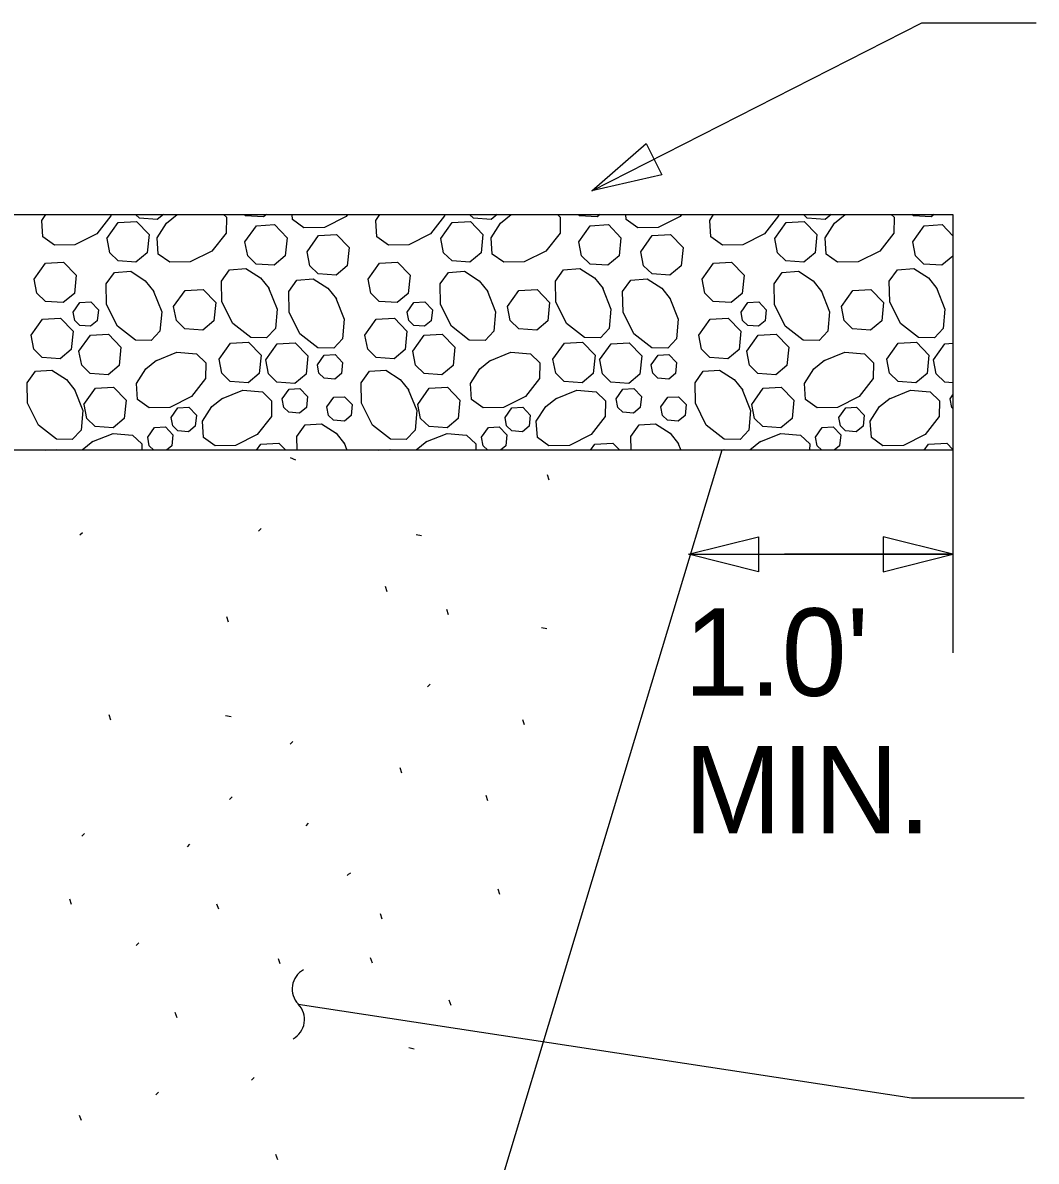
# Model space of a CAD drawing. Extents: x 9786.6 to 9853.1, y 9958.7 to 10011.2.
# Drawn here: x 9816.93 to 9829.04, y 9997.08 to 10010.67 of the extents above; entities that cross this region are included whole.
import ezdxf

# ---------------------------------------------------------------- set-up
doc = ezdxf.new("R2010")
doc.units = 0
for name, color, linetype in [('Default', 7, 'Continuous'), ('G-ANNO-TEXT', 7, 'Continuous'), ('G-ANNO-TTXT', 7, 'Continuous'), ('G-DETL-LINE', 7, 'Continuous'), ('G-DETL-OTLN', 7, 'Continuous'), ('G-DETL-PATT', 7, 'Continuous')]:
    doc.layers.add(name, color=color, linetype=linetype)

# ---------------------------------------------------------------- blocks, each defined once
blk = doc.blocks.new('TERARR')
at = {"layer": 'Default'}
blk.add_lwpolyline([(-0.667, 0.167), (0, 0), (-0.667, -0.167)], close=True, dxfattribs=at)
blk = doc.blocks.new('TERBRK')
at = {"layer": 'Default'}
for centre, start, end in [((0.125, 0.167), 126.8699, 233.1301), ((-0.125, -0.167), 306.8699, 53.1301)]:
    blk.add_arc(centre, 0.208, start, end, dxfattribs=at)

msp = doc.modelspace()

# ---------------------------------------------------------------- linework, layer by layer
at = {"layer": 'Default'}
for points in [[(9818.77, 10008.375), (9818.792, 10008.384)], [(9822.758, 10008.375), (9822.78, 10008.384)], [(9823.833, 10008.384), (9823.797, 10008.354), (9823.583, 10008.369), (9823.568, 10008.384)], [(9826.746, 10008.375), (9826.768, 10008.384)], [(9817.201, 10005.569), (9817.332, 10005.576), (9817.339, 10005.569)], [(9821.189, 10005.569), (9821.32, 10005.576), (9821.327, 10005.569)], [(9825.177, 10005.569), (9825.308, 10005.576), (9825.315, 10005.569)]]:
    msp.add_lwpolyline(points, dxfattribs=at)
at = {"layer": 'G-ANNO-TEXT'}
for p, q in [((9828.045, 10005.569), (9828.045, 10003.15)), ((9824.888, 10004.326), (9828.045, 10004.326)), ((9828.045, 10004.326), (9826.035, 10004.326))]:
    msp.add_line(p, q, dxfattribs=at)
msp.add_lwpolyline([(9823.731, 10008.667), (9827.674, 10010.673), (9829.04, 10010.673)], dxfattribs=at)
at = {"layer": 'G-ANNO-TTXT'}
msp.add_lwpolyline([(9820.226, 9998.953), (9827.551, 9997.834), (9828.894, 9997.834)], dxfattribs=at)
at = {"layer": 'G-DETL-LINE'}
msp.add_lwpolyline([(9804.677, 10008.384), (9828.045, 10008.384), (9828.045, 10005.569), (9804.677, 10005.569)], close=True, dxfattribs=at)
at = {"layer": 'G-DETL-OTLN'}
msp.add_lwpolyline([(9825.286, 10005.569), (9820.093, 9988.373), (9820.093, 9984.842), (9813.116, 9984.842), (9813.116, 9988.373), (9807.923, 10005.569)], dxfattribs=at)
at = {"layer": 'G-DETL-PATT'}
for p, q in [((9820.129, 10005.483), (9820.192, 10005.452)), ((9823.222, 10005.212), (9823.201, 10005.275)), ((9817.617, 10004.557), (9817.648, 10004.588)), ((9819.751, 10004.603), (9819.782, 10004.635)), ((9821.634, 10004.564), (9821.699, 10004.55)), ((9821.287, 10003.877), (9821.266, 10003.94)), ((9822.021, 10003.604), (9822, 10003.667)), ((9819.393, 10003.516), (9819.372, 10003.579)), ((9823.129, 10003.453), (9823.193, 10003.439)), ((9821.768, 10002.744), (9821.8, 10002.775)), ((9817.987, 10002.347), (9817.966, 10002.41)), ((9819.358, 10002.401), (9819.423, 10002.387)), ((9822.929, 10002.288), (9822.908, 10002.351)), ((9820.129, 10002.058), (9820.16, 10002.09)), ((9821.463, 10001.713), (9821.442, 10001.776)), ((9819.405, 10001.399), (9819.436, 10001.43)), ((9822.49, 10001.382), (9822.469, 10001.445)), ((9820.318, 10001.084), (9820.349, 10001.116)), ((9817.641, 10000.959), (9817.672, 10000.99)), ((9818.901, 10000.833), (9818.932, 10000.864)), ((9820.821, 10000.504), (9820.809, 10000.49)), ((9820.848, 10000.518), (9820.821, 10000.504)), ((9817.517, 10000.146), (9817.496, 10000.209)), ((9822.635, 10000.263), (9822.614, 10000.326)), ((9819.275, 10000.087), (9819.254, 10000.15)), ((9821.228, 9999.97), (9821.207, 10000.033)), ((9818.291, 9999.656), (9818.322, 9999.687)), ((9820.009, 9999.435), (9819.988, 9999.497)), ((9821.111, 9999.444), (9821.09, 9999.507)), ((9822.05, 9998.937), (9822.029, 9999)), ((9818.778, 9998.791), (9818.757, 9998.854)), ((9821.546, 9998.436), (9821.611, 9998.422)), ((9819.668, 9998.048), (9819.7, 9998.079)), ((9818.525, 9997.872), (9818.557, 9997.904)), ((9817.635, 9997.563), (9817.614, 9997.626)), ((9819.98, 9997.095), (9819.958, 9997.158))]:
    msp.add_line(p, q, dxfattribs=at)
for points in [[(9817.986, 10008.384), (9817.986, 10008.366), (9817.818, 10008.152), (9817.558, 10008.022), (9817.314, 10008.018), (9817.176, 10008.115), (9817.163, 10008.31), (9817.21, 10008.384)], [(9818.614, 10008.384), (9818.542, 10008.324), (9818.329, 10008.34), (9818.283, 10008.384)], [(9819.332, 10008.384), (9819.367, 10008.35), (9819.363, 10008.161), (9819.195, 10007.947), (9818.936, 10007.817), (9818.691, 10007.813), (9818.553, 10007.91), (9818.54, 10008.105), (9818.652, 10008.28), (9818.78, 10008.382)], [(9819.845, 10008.384), (9819.809, 10008.354), (9819.595, 10008.369), (9819.58, 10008.384)], [(9820.815, 10008.384), (9820.796, 10008.36), (9820.537, 10008.23), (9820.292, 10008.226), (9820.155, 10008.324), (9820.151, 10008.384)], [(9821.975, 10008.384), (9821.974, 10008.366), (9821.806, 10008.152), (9821.547, 10008.022), (9821.302, 10008.018), (9821.164, 10008.115), (9821.151, 10008.31), (9821.199, 10008.384)], [(9822.602, 10008.384), (9822.531, 10008.324), (9822.317, 10008.34), (9822.272, 10008.384)], [(9823.32, 10008.384), (9823.355, 10008.35), (9823.352, 10008.161), (9823.184, 10007.947), (9822.924, 10007.817), (9822.679, 10007.813), (9822.542, 10007.91), (9822.529, 10008.105), (9822.64, 10008.28), (9822.768, 10008.382)], [(9824.804, 10008.384), (9824.785, 10008.36), (9824.525, 10008.23), (9824.281, 10008.226), (9824.143, 10008.324), (9824.139, 10008.384)], [(9825.963, 10008.384), (9825.963, 10008.366), (9825.795, 10008.152), (9825.535, 10008.022), (9825.291, 10008.018), (9825.153, 10008.115), (9825.14, 10008.31), (9825.187, 10008.384)], [(9826.59, 10008.384), (9826.519, 10008.324), (9826.305, 10008.34), (9826.26, 10008.384)], [(9827.308, 10008.384), (9827.343, 10008.35), (9827.34, 10008.161), (9827.172, 10007.947), (9826.912, 10007.817), (9826.668, 10007.813), (9826.53, 10007.91), (9826.517, 10008.105), (9826.629, 10008.28), (9826.757, 10008.382)], [(9827.822, 10008.384), (9827.785, 10008.354), (9827.572, 10008.369), (9827.556, 10008.384)], [(9817.94, 10008.095), (9818.076, 10008.288), (9818.292, 10008.3), (9818.443, 10008.144), (9818.421, 10007.926), (9818.287, 10007.814), (9818.074, 10007.83), (9817.973, 10007.927), (9817.941, 10008.095)], [(9819.589, 10008.057), (9819.725, 10008.25), (9819.941, 10008.262), (9820.091, 10008.106), (9820.07, 10007.888), (9819.936, 10007.777), (9819.722, 10007.792), (9819.622, 10007.889), (9819.589, 10008.057)], [(9821.929, 10008.095), (9822.064, 10008.288), (9822.281, 10008.3), (9822.431, 10008.144), (9822.409, 10007.926), (9822.276, 10007.814), (9822.062, 10007.83), (9821.961, 10007.927), (9821.929, 10008.095)], [(9823.577, 10008.057), (9823.713, 10008.25), (9823.929, 10008.262), (9824.08, 10008.106), (9824.058, 10007.888), (9823.924, 10007.777), (9823.711, 10007.792), (9823.61, 10007.889), (9823.578, 10008.057)], [(9825.917, 10008.095), (9826.053, 10008.288), (9826.269, 10008.3), (9826.419, 10008.144), (9826.398, 10007.926), (9826.264, 10007.814), (9826.05, 10007.83), (9825.95, 10007.927), (9825.917, 10008.095)], [(9827.566, 10008.057), (9827.701, 10008.25), (9827.918, 10008.262), (9828.045, 10008.13)], [(9820.33, 10007.939), (9820.466, 10008.132), (9820.682, 10008.144), (9820.832, 10007.988), (9820.81, 10007.77), (9820.677, 10007.659), (9820.463, 10007.674), (9820.363, 10007.771), (9820.33, 10007.939)], [(9824.318, 10007.939), (9824.454, 10008.132), (9824.67, 10008.144), (9824.821, 10007.988), (9824.799, 10007.77), (9824.665, 10007.659), (9824.452, 10007.674), (9824.351, 10007.771), (9824.318, 10007.939)], [(9828.045, 10007.886), (9827.913, 10007.777), (9827.699, 10007.792), (9827.599, 10007.889), (9827.566, 10008.057)], [(9817.071, 10007.611), (9817.207, 10007.804), (9817.423, 10007.816), (9817.574, 10007.66), (9817.552, 10007.442), (9817.418, 10007.331), (9817.205, 10007.346), (9817.104, 10007.444), (9817.072, 10007.611)], [(9821.06, 10007.611), (9821.195, 10007.804), (9821.412, 10007.816), (9821.562, 10007.66), (9821.54, 10007.442), (9821.407, 10007.331), (9821.193, 10007.346), (9821.093, 10007.444), (9821.06, 10007.611)], [(9825.048, 10007.611), (9825.184, 10007.804), (9825.4, 10007.816), (9825.55, 10007.66), (9825.529, 10007.442), (9825.395, 10007.331), (9825.181, 10007.346), (9825.081, 10007.444), (9825.048, 10007.611)], [(9818.494, 10007.475), (9818.594, 10007.222), (9818.574, 10006.989), (9818.469, 10006.878), (9818.28, 10006.882), (9818.065, 10007.05), (9817.936, 10007.309), (9817.931, 10007.554), (9818.029, 10007.692), (9818.224, 10007.705), (9818.398, 10007.593), (9818.5, 10007.465)], [(9819.871, 10007.508), (9819.972, 10007.254), (9819.952, 10007.022), (9819.846, 10006.911), (9819.657, 10006.914), (9819.443, 10007.082), (9819.313, 10007.342), (9819.309, 10007.587), (9819.406, 10007.724), (9819.601, 10007.737), (9819.776, 10007.626), (9819.878, 10007.498)], [(9822.482, 10007.475), (9822.583, 10007.222), (9822.563, 10006.989), (9822.457, 10006.878), (9822.268, 10006.882), (9822.054, 10007.05), (9821.924, 10007.309), (9821.92, 10007.554), (9822.018, 10007.692), (9822.212, 10007.705), (9822.387, 10007.593), (9822.489, 10007.465)], [(9823.859, 10007.508), (9823.96, 10007.254), (9823.94, 10007.022), (9823.835, 10006.911), (9823.646, 10006.914), (9823.431, 10007.082), (9823.301, 10007.342), (9823.297, 10007.587), (9823.395, 10007.724), (9823.59, 10007.737), (9823.764, 10007.626), (9823.866, 10007.498)], [(9826.471, 10007.475), (9826.571, 10007.222), (9826.551, 10006.989), (9826.446, 10006.878), (9826.257, 10006.882), (9826.042, 10007.05), (9825.912, 10007.309), (9825.908, 10007.554), (9826.006, 10007.692), (9826.201, 10007.705), (9826.375, 10007.593), (9826.477, 10007.465)], [(9827.848, 10007.508), (9827.948, 10007.254), (9827.928, 10007.022), (9827.823, 10006.911), (9827.634, 10006.914), (9827.419, 10007.082), (9827.29, 10007.342), (9827.285, 10007.587), (9827.383, 10007.724), (9827.578, 10007.737), (9827.752, 10007.626), (9827.854, 10007.498)], [(9820.674, 10007.385), (9820.775, 10007.132), (9820.755, 10006.899), (9820.65, 10006.788), (9820.461, 10006.791), (9820.246, 10006.959), (9820.116, 10007.219), (9820.112, 10007.464), (9820.21, 10007.601), (9820.405, 10007.614), (9820.579, 10007.503), (9820.681, 10007.375)], [(9824.663, 10007.385), (9824.763, 10007.132), (9824.743, 10006.899), (9824.638, 10006.788), (9824.449, 10006.791), (9824.234, 10006.959), (9824.105, 10007.219), (9824.1, 10007.464), (9824.198, 10007.601), (9824.393, 10007.614), (9824.567, 10007.503), (9824.669, 10007.375)], [(9818.737, 10007.283), (9818.873, 10007.476), (9819.089, 10007.488), (9819.24, 10007.333), (9819.218, 10007.114), (9819.084, 10007.003), (9818.871, 10007.018), (9818.77, 10007.116), (9818.737, 10007.283)], [(9822.726, 10007.283), (9822.861, 10007.476), (9823.078, 10007.488), (9823.228, 10007.333), (9823.206, 10007.114), (9823.073, 10007.003), (9822.859, 10007.018), (9822.758, 10007.116), (9822.726, 10007.283)], [(9826.714, 10007.283), (9826.85, 10007.476), (9827.066, 10007.488), (9827.216, 10007.333), (9827.195, 10007.114), (9827.061, 10007.003), (9826.847, 10007.018), (9826.747, 10007.116), (9826.714, 10007.283)], [(9817.537, 10007.216), (9817.618, 10007.332), (9817.748, 10007.339), (9817.838, 10007.246), (9817.825, 10007.115), (9817.745, 10007.048), (9817.617, 10007.057), (9817.557, 10007.116), (9817.537, 10007.216)], [(9821.525, 10007.216), (9821.607, 10007.332), (9821.737, 10007.339), (9821.827, 10007.246), (9821.814, 10007.115), (9821.734, 10007.048), (9821.605, 10007.057), (9821.545, 10007.116), (9821.525, 10007.216)], [(9825.514, 10007.216), (9825.595, 10007.332), (9825.725, 10007.339), (9825.815, 10007.246), (9825.802, 10007.115), (9825.722, 10007.048), (9825.594, 10007.057), (9825.533, 10007.116), (9825.514, 10007.216)], [(9817.034, 10006.942), (9817.169, 10007.135), (9817.385, 10007.147), (9817.536, 10006.991), (9817.514, 10006.773), (9817.38, 10006.661), (9817.167, 10006.677), (9817.066, 10006.774), (9817.034, 10006.942)], [(9821.022, 10006.942), (9821.157, 10007.135), (9821.374, 10007.147), (9821.524, 10006.991), (9821.502, 10006.773), (9821.369, 10006.661), (9821.155, 10006.677), (9821.055, 10006.774), (9821.022, 10006.942)], [(9825.01, 10006.942), (9825.146, 10007.135), (9825.362, 10007.147), (9825.512, 10006.991), (9825.491, 10006.773), (9825.357, 10006.661), (9825.143, 10006.677), (9825.043, 10006.774), (9825.01, 10006.942)], [(9817.606, 10006.75), (9817.742, 10006.943), (9817.958, 10006.956), (9818.108, 10006.8), (9818.087, 10006.581), (9817.953, 10006.47), (9817.739, 10006.485), (9817.639, 10006.583), (9817.606, 10006.75)], [(9821.594, 10006.75), (9821.73, 10006.943), (9821.946, 10006.956), (9822.097, 10006.8), (9822.075, 10006.581), (9821.941, 10006.47), (9821.728, 10006.485), (9821.627, 10006.583), (9821.595, 10006.75)], [(9825.583, 10006.75), (9825.718, 10006.943), (9825.935, 10006.956), (9826.085, 10006.8), (9826.063, 10006.581), (9825.93, 10006.47), (9825.716, 10006.485), (9825.615, 10006.583), (9825.583, 10006.75)], [(9818.524, 10006.637), (9818.777, 10006.738), (9819.01, 10006.718), (9819.121, 10006.612), (9819.117, 10006.424), (9818.949, 10006.209), (9818.69, 10006.079), (9818.445, 10006.075), (9818.307, 10006.173), (9818.294, 10006.367), (9818.406, 10006.542), (9818.534, 10006.644)], [(9819.28, 10006.655), (9819.415, 10006.848), (9819.632, 10006.86), (9819.782, 10006.704), (9819.76, 10006.486), (9819.627, 10006.374), (9819.413, 10006.39), (9819.312, 10006.487), (9819.28, 10006.655)], [(9819.837, 10006.647), (9819.973, 10006.84), (9820.189, 10006.852), (9820.339, 10006.696), (9820.318, 10006.477), (9820.184, 10006.366), (9819.97, 10006.382), (9819.87, 10006.479), (9819.837, 10006.647)], [(9822.512, 10006.637), (9822.766, 10006.738), (9822.998, 10006.718), (9823.109, 10006.612), (9823.106, 10006.424), (9822.938, 10006.209), (9822.678, 10006.079), (9822.433, 10006.075), (9822.296, 10006.173), (9822.283, 10006.367), (9822.394, 10006.542), (9822.522, 10006.644)], [(9823.268, 10006.655), (9823.404, 10006.848), (9823.62, 10006.86), (9823.77, 10006.704), (9823.748, 10006.486), (9823.615, 10006.374), (9823.401, 10006.39), (9823.301, 10006.487), (9823.268, 10006.655)], [(9823.825, 10006.647), (9823.961, 10006.84), (9824.177, 10006.852), (9824.328, 10006.696), (9824.306, 10006.477), (9824.172, 10006.366), (9823.959, 10006.382), (9823.858, 10006.479), (9823.826, 10006.647)], [(9826.5, 10006.637), (9826.754, 10006.738), (9826.987, 10006.718), (9827.098, 10006.612), (9827.094, 10006.424), (9826.926, 10006.209), (9826.666, 10006.079), (9826.422, 10006.075), (9826.284, 10006.173), (9826.271, 10006.367), (9826.383, 10006.542), (9826.511, 10006.644)], [(9827.256, 10006.655), (9827.392, 10006.848), (9827.608, 10006.86), (9827.759, 10006.704), (9827.737, 10006.486), (9827.603, 10006.374), (9827.39, 10006.39), (9827.289, 10006.487), (9827.256, 10006.655)], [(9827.814, 10006.647), (9827.949, 10006.84), (9828.045, 10006.845)], [(9820.454, 10006.587), (9820.535, 10006.703), (9820.665, 10006.71), (9820.755, 10006.617), (9820.742, 10006.486), (9820.662, 10006.419), (9820.534, 10006.428), (9820.473, 10006.487), (9820.454, 10006.587)], [(9824.442, 10006.587), (9824.523, 10006.703), (9824.653, 10006.71), (9824.743, 10006.617), (9824.73, 10006.486), (9824.65, 10006.419), (9824.522, 10006.428), (9824.462, 10006.487), (9824.442, 10006.587)], [(9828.045, 10006.375), (9827.947, 10006.382), (9827.846, 10006.479), (9827.814, 10006.647)], [(9817.551, 10006.295), (9817.652, 10006.041), (9817.632, 10005.808), (9817.526, 10005.698), (9817.337, 10005.701), (9817.123, 10005.869), (9816.993, 10006.129), (9816.989, 10006.373), (9817.086, 10006.511), (9817.281, 10006.524), (9817.456, 10006.412), (9817.558, 10006.284)], [(9821.54, 10006.295), (9821.64, 10006.041), (9821.62, 10005.808), (9821.515, 10005.698), (9821.326, 10005.701), (9821.111, 10005.869), (9820.981, 10006.129), (9820.977, 10006.373), (9821.075, 10006.511), (9821.27, 10006.524), (9821.444, 10006.412), (9821.546, 10006.284)], [(9825.528, 10006.295), (9825.628, 10006.041), (9825.608, 10005.808), (9825.503, 10005.698), (9825.314, 10005.701), (9825.099, 10005.869), (9824.97, 10006.129), (9824.965, 10006.373), (9825.063, 10006.511), (9825.258, 10006.524), (9825.432, 10006.412), (9825.534, 10006.284)], [(9817.666, 10006.116), (9817.802, 10006.309), (9818.018, 10006.321), (9818.169, 10006.165), (9818.147, 10005.947), (9818.013, 10005.836), (9817.8, 10005.851), (9817.699, 10005.949), (9817.667, 10006.116)], [(9821.655, 10006.116), (9821.79, 10006.309), (9822.007, 10006.321), (9822.157, 10006.165), (9822.135, 10005.947), (9822.002, 10005.836), (9821.788, 10005.851), (9821.687, 10005.949), (9821.655, 10006.116)], [(9825.643, 10006.116), (9825.779, 10006.309), (9825.995, 10006.321), (9826.145, 10006.165), (9826.124, 10005.947), (9825.99, 10005.836), (9825.776, 10005.851), (9825.676, 10005.949), (9825.643, 10006.116)], [(9819.31, 10006.184), (9819.564, 10006.285), (9819.797, 10006.265), (9819.907, 10006.16), (9819.904, 10005.971), (9819.736, 10005.756), (9819.476, 10005.626), (9819.232, 10005.622), (9819.094, 10005.72), (9819.081, 10005.915), (9819.193, 10006.089), (9819.321, 10006.191)], [(9820.034, 10006.181), (9820.116, 10006.296), (9820.245, 10006.304), (9820.336, 10006.21), (9820.323, 10006.079), (9820.242, 10006.012), (9820.114, 10006.022), (9820.054, 10006.08), (9820.034, 10006.181)], [(9820.568, 10006.085), (9820.649, 10006.201), (9820.779, 10006.208), (9820.869, 10006.115), (9820.856, 10005.984), (9820.776, 10005.917), (9820.648, 10005.926), (9820.588, 10005.985), (9820.568, 10006.085)], [(9823.299, 10006.184), (9823.552, 10006.285), (9823.785, 10006.265), (9823.896, 10006.16), (9823.892, 10005.971), (9823.724, 10005.756), (9823.465, 10005.626), (9823.22, 10005.622), (9823.082, 10005.72), (9823.069, 10005.915), (9823.181, 10006.089), (9823.309, 10006.191)], [(9824.023, 10006.181), (9824.104, 10006.296), (9824.234, 10006.304), (9824.324, 10006.21), (9824.311, 10006.079), (9824.231, 10006.012), (9824.103, 10006.022), (9824.042, 10006.08), (9824.023, 10006.181)], [(9824.556, 10006.085), (9824.638, 10006.201), (9824.767, 10006.208), (9824.858, 10006.115), (9824.845, 10005.984), (9824.764, 10005.917), (9824.636, 10005.926), (9824.576, 10005.985), (9824.556, 10006.085)], [(9827.287, 10006.184), (9827.54, 10006.285), (9827.773, 10006.265), (9827.884, 10006.16), (9827.88, 10005.971), (9827.712, 10005.756), (9827.453, 10005.626), (9827.208, 10005.622), (9827.071, 10005.72), (9827.057, 10005.915), (9827.169, 10006.089), (9827.297, 10006.191)], [(9828.011, 10006.181), (9828.045, 10006.229)], [(9818.706, 10005.958), (9818.788, 10006.074), (9818.917, 10006.081), (9819.008, 10005.988), (9818.995, 10005.857), (9818.914, 10005.79), (9818.786, 10005.799), (9818.726, 10005.858), (9818.706, 10005.958)], [(9822.695, 10005.958), (9822.776, 10006.074), (9822.906, 10006.081), (9822.996, 10005.988), (9822.983, 10005.857), (9822.903, 10005.79), (9822.775, 10005.799), (9822.714, 10005.858), (9822.695, 10005.958)], [(9826.683, 10005.958), (9826.764, 10006.074), (9826.894, 10006.081), (9826.984, 10005.988), (9826.971, 10005.857), (9826.891, 10005.79), (9826.763, 10005.799), (9826.703, 10005.858), (9826.683, 10005.958)], [(9828.045, 10006.066), (9828.031, 10006.08), (9828.011, 10006.181)], [(9818.427, 10005.723), (9818.508, 10005.839), (9818.638, 10005.846), (9818.728, 10005.753), (9818.715, 10005.621), (9818.651, 10005.569)], [(9820.213, 10005.569), (9820.21, 10005.734), (9820.308, 10005.872), (9820.503, 10005.885), (9820.677, 10005.773), (9820.779, 10005.645)], [(9822.415, 10005.723), (9822.496, 10005.839), (9822.626, 10005.846), (9822.716, 10005.753), (9822.703, 10005.621), (9822.64, 10005.569)], [(9824.201, 10005.569), (9824.199, 10005.734), (9824.296, 10005.872), (9824.491, 10005.885), (9824.666, 10005.773), (9824.768, 10005.645)], [(9826.403, 10005.723), (9826.485, 10005.839), (9826.614, 10005.846), (9826.705, 10005.753), (9826.692, 10005.621), (9826.628, 10005.569)], [(9817.641, 10005.569), (9817.643, 10005.573), (9817.771, 10005.675)], [(9817.761, 10005.668), (9818.015, 10005.769), (9818.247, 10005.748), (9818.358, 10005.643), (9818.357, 10005.569)], [(9818.502, 10005.569), (9818.446, 10005.623), (9818.427, 10005.723)], [(9819.726, 10005.569), (9819.778, 10005.642), (9819.994, 10005.654), (9820.076, 10005.569)], [(9820.773, 10005.655), (9820.807, 10005.569)], [(9821.629, 10005.569), (9821.632, 10005.573), (9821.76, 10005.675)], [(9821.749, 10005.668), (9822.003, 10005.769), (9822.236, 10005.748), (9822.346, 10005.643), (9822.345, 10005.569)], [(9822.49, 10005.569), (9822.435, 10005.623), (9822.415, 10005.723)], [(9823.715, 10005.569), (9823.766, 10005.642), (9823.982, 10005.654), (9824.065, 10005.569)], [(9824.761, 10005.655), (9824.796, 10005.569)], [(9825.618, 10005.569), (9825.62, 10005.573), (9825.748, 10005.675)], [(9825.738, 10005.668), (9825.991, 10005.769), (9826.224, 10005.748), (9826.335, 10005.643), (9826.333, 10005.569)], [(9826.479, 10005.569), (9826.423, 10005.623), (9826.403, 10005.723)], [(9827.703, 10005.569), (9827.754, 10005.642), (9827.971, 10005.654), (9828.045, 10005.577)]]:
    msp.add_lwpolyline(points, dxfattribs=at)

# ---------------------------------------------------------------- block references
at = {"layer": 'G-ANNO-TEXT'}
for p, xscale, yscale, rotation in [((9823.731, 10008.667), 1.2500000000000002, 1.2499999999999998, -153.0403892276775), ((9824.888, 10004.326), 1.25, 1.25, 180)]:
    msp.add_blockref('TERARR', p, dxfattribs=dict(at, xscale=xscale, yscale=yscale, rotation=rotation))
at = {"layer": 'G-ANNO-TEXT', "xscale": 1.25, "yscale": -1.25}
msp.add_blockref('TERARR', (9828.045, 10004.326), dxfattribs=at)
at = {"layer": 'G-ANNO-TTXT', "xscale": 1.2500000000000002, "yscale": 1.2500000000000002, "rotation": 171.31749501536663}
msp.add_blockref('TERBRK', (9820.226, 9998.953), dxfattribs=at)

# ---------------------------------------------------------------- texts
at = {"layer": 'G-ANNO-TEXT'}
for s, p in [("1.0' ", (9824.835, 10002.636)), ('MIN.', (9824.835, 10000.992))]:
    msp.add_text(s, height=1.044, dxfattribs=at).set_placement(p)

doc.saveas('drawing.dxf')
